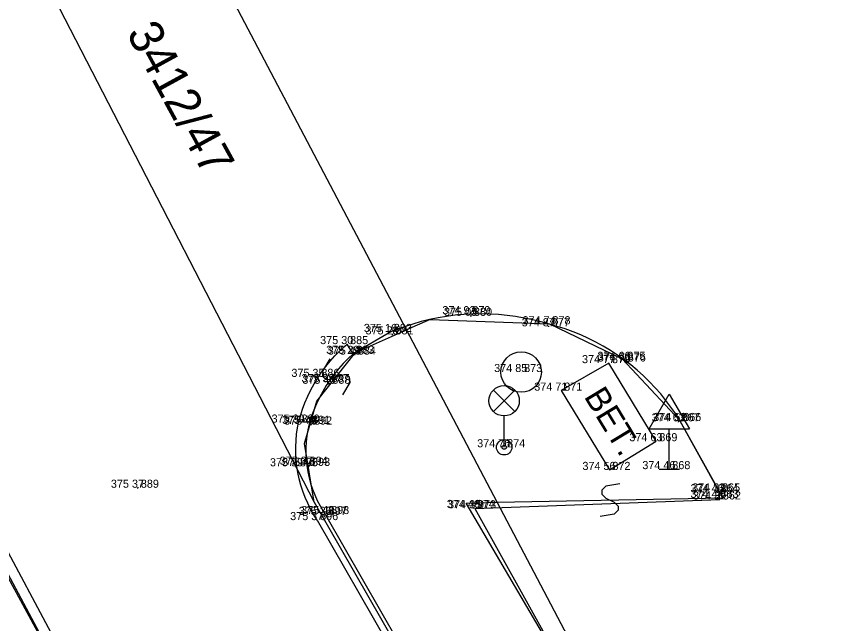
# Model space of a CAD drawing. Extents: x -601196 to -600262, y -1082523 to -1081922.
# Drawn here: x -600574.7 to -600554.22, y -1082123.8 to -1082108.8 of the extents above; entities that cross this region are included whole.
import ezdxf

# ---------------------------------------------------------------- set-up
doc = ezdxf.new("R2010")
doc.units = 0
for name, color, linetype in [('Vrstva 1', 7, 'Continuous'), ('Vrstva 10', 7, 'Continuous'), ('Vrstva 11', 7, 'Continuous'), ('Vrstva 2', 7, 'Continuous'), ('Vrstva 20', 7, 'Continuous'), ('Vrstva 27', 7, 'Continuous'), ('Vrstva 3', 7, 'Continuous'), ('Vrstva 33', 7, 'Continuous'), ('Vrstva 34', 7, 'Continuous'), ('Vrstva 40', 7, 'Continuous'), ('Vrstva 47', 7, 'Continuous')]:
    doc.layers.add(name, color=color, linetype=linetype)

msp = doc.modelspace()

# ---------------------------------------------------------------- linework, layer by layer
at = {"layer": 'Vrstva 1'}
for p, q in [((-600563.51, -1082116.16), (-600563.51, -1082116.16)), ((-600563.47, -1082116.2), (-600563.47, -1082116.2)), ((-600561.55, -1082116.46), (-600561.55, -1082116.46)), ((-600561.53, -1082116.41), (-600561.53, -1082116.41)), ((-600565.45, -1082116.6), (-600565.45, -1082116.6)), ((-600565.41, -1082116.66), (-600565.41, -1082116.66)), ((-600566.53, -1082116.9), (-600566.53, -1082116.9)), ((-600566.38, -1082117.14), (-600566.38, -1082117.14)), ((-600566.34, -1082117.16), (-600566.34, -1082117.16)), ((-600559.68, -1082117.29), (-600559.68, -1082117.29)), ((-600560.06, -1082117.37), (-600560.06, -1082117.37)), ((-600559.67, -1082117.33), (-600559.67, -1082117.33)), ((-600567.24, -1082117.71), (-600567.24, -1082117.71)), ((-600562.23, -1082117.59), (-600562.23, -1082117.59)), ((-600566.99, -1082117.84), (-600566.99, -1082117.84)), ((-600566.97, -1082117.88), (-600566.97, -1082117.88)), ((-600561.24, -1082118.05), (-600561.24, -1082118.05)), ((-600567.73, -1082118.84), (-600567.73, -1082118.84)), ((-600567.47, -1082118.87), (-600567.47, -1082118.87)), ((-600567.42, -1082118.89), (-600567.42, -1082118.89)), ((-600558.34, -1082118.81), (-600558.34, -1082118.81)), ((-600558.3, -1082118.8), (-600558.3, -1082118.8)), ((-600558.89, -1082119.3), (-600558.89, -1082119.3)), ((-600562.65, -1082119.45), (-600562.65, -1082119.45)), ((-600567.77, -1082119.92), (-600567.77, -1082119.92)), ((-600567.53, -1082119.88), (-600567.53, -1082119.88)), ((-600567.47, -1082119.91), (-600567.47, -1082119.91)), ((-600560.05, -1082120.01), (-600560.05, -1082120.01)), ((-600558.57, -1082119.99), (-600558.57, -1082119.99)), ((-600571.7, -1082120.45), (-600571.7, -1082120.45)), ((-600557.38, -1082120.56), (-600557.38, -1082120.56)), ((-600557.34, -1082120.54), (-600557.34, -1082120.54)), ((-600557.38, -1082120.7), (-600557.38, -1082120.7)), ((-600557.32, -1082120.74), (-600557.32, -1082120.74)), ((-600563.4, -1082120.95), (-600563.4, -1082120.95)), ((-600563.37, -1082120.96), (-600563.37, -1082120.96)), ((-600567.06, -1082121.12), (-600567.06, -1082121.12)), ((-600567, -1082121.1), (-600567, -1082121.1)), ((-600567.27, -1082121.25), (-600567.27, -1082121.25))]:
    msp.add_line(p, q, dxfattribs=at)
at = {"layer": 'Vrstva 10'}
for p, q in [((-600565.45, -1082116.6), (-600566.38, -1082117.14)), ((-600557.34, -1082120.54), (-600558.3, -1082118.8)), ((-600557.32, -1082120.74), (-600557.34, -1082120.54)), ((-600563.37, -1082120.96), (-600557.32, -1082120.74)), ((-600567.11, -1082137.17), (-600575.77, -1082120.97)), ((-600563.37, -1082120.96), (-600560.5, -1082126.14)), ((-600567.06, -1082121.12), (-600561.14, -1082131.44))]:
    msp.add_line(p, q, dxfattribs=at)
for points in [[(-600561.53, -1082116.41), (-600561.736, -1082116.351), (-600561.944, -1082116.299), (-600562.154, -1082116.255), (-600562.366, -1082116.219), (-600562.578, -1082116.19), (-600562.791, -1082116.17), (-600563.005, -1082116.158), (-600563.219, -1082116.153), (-600563.433, -1082116.157), (-600563.647, -1082116.168), (-600563.86, -1082116.188), (-600564.072, -1082116.215), (-600564.283, -1082116.25), (-600564.492, -1082116.293), (-600564.699, -1082116.344), (-600564.905, -1082116.403), (-600565.108, -1082116.469), (-600565.308, -1082116.542), (-600565.45, -1082116.6)], [(-600558.3, -1082118.8), (-600558.41, -1082118.626), (-600558.528, -1082118.457), (-600558.651, -1082118.292), (-600558.781, -1082118.132), (-600558.917, -1082117.978), (-600559.059, -1082117.828), (-600559.207, -1082117.684), (-600559.36, -1082117.546), (-600559.518, -1082117.414), (-600559.682, -1082117.289), (-600559.85, -1082117.169), (-600560.023, -1082117.056), (-600560.2, -1082116.95), (-600560.381, -1082116.851), (-600560.565, -1082116.759), (-600560.753, -1082116.674), (-600560.945, -1082116.597), (-600561.139, -1082116.526), (-600561.336, -1082116.464), (-600561.53, -1082116.41)], [(-600566.38, -1082117.14), (-600566.505, -1082117.257), (-600566.625, -1082117.38), (-600566.739, -1082117.508), (-600566.847, -1082117.641), (-600566.948, -1082117.779), (-600567.044, -1082117.922), (-600567.132, -1082118.069), (-600567.213, -1082118.22), (-600567.288, -1082118.375), (-600567.355, -1082118.533), (-600567.414, -1082118.694), (-600567.466, -1082118.858), (-600567.47, -1082118.87)], [(-600567.47, -1082118.87), (-600567.502, -1082119.016), (-600567.526, -1082119.163), (-600567.542, -1082119.312), (-600567.55, -1082119.461), (-600567.55, -1082119.611), (-600567.542, -1082119.76), (-600567.526, -1082119.908), (-600567.503, -1082120.056), (-600567.471, -1082120.202), (-600567.432, -1082120.346), (-600567.384, -1082120.488), (-600567.33, -1082120.627), (-600567.268, -1082120.763), (-600567.199, -1082120.896), (-600567.123, -1082121.025), (-600567.06, -1082121.12)]]:
    msp.add_lwpolyline(points, dxfattribs=at)
at = {"layer": 'Vrstva 11'}
for p, q in [((-600566.38, -1082117.14), (-600566.53, -1082116.9)), ((-600560.06, -1082117.37), (-600561.24, -1082118.05)), ((-600558.89, -1082119.3), (-600560.06, -1082117.37)), ((-600561.24, -1082118.05), (-600560.05, -1082120.01)), ((-600560.05, -1082120.01), (-600558.89, -1082119.3)), ((-600566.89, -1082137.01), (-600575.53, -1082120.88)), ((-600567.27, -1082121.25), (-600561.37, -1082131.55))]:
    msp.add_line(p, q, dxfattribs=at)
for points in [[(-600567.73, -1082118.84), (-600567.684, -1082118.673), (-600567.631, -1082118.509), (-600567.571, -1082118.347), (-600567.502, -1082118.188), (-600567.427, -1082118.033), (-600567.345, -1082117.881), (-600567.255, -1082117.734), (-600567.159, -1082117.59), (-600567.056, -1082117.451), (-600566.947, -1082117.317), (-600566.832, -1082117.189), (-600566.711, -1082117.065), (-600566.585, -1082116.948), (-600566.53, -1082116.9)], [(-600567.27, -1082121.25), (-600567.355, -1082121.115), (-600567.432, -1082120.976), (-600567.503, -1082120.833), (-600567.567, -1082120.687), (-600567.623, -1082120.538), (-600567.671, -1082120.386), (-600567.712, -1082120.232), (-600567.745, -1082120.076), (-600567.77, -1082119.919), (-600567.787, -1082119.761), (-600567.797, -1082119.602), (-600567.798, -1082119.442), (-600567.791, -1082119.283), (-600567.777, -1082119.124), (-600567.754, -1082118.967), (-600567.73, -1082118.84)]]:
    msp.add_lwpolyline(points, dxfattribs=at)
at = {"layer": 'Vrstva 20'}
for p, q in [((-600563.48, -1082116.2), (-600563.46, -1082116.2)), ((-600563.47, -1082116.185), (-600563.47, -1082116.2)), ((-600563.47, -1082116.215), (-600563.47, -1082116.2)), ((-600561.56, -1082116.46), (-600561.54, -1082116.46)), ((-600561.55, -1082116.445), (-600561.55, -1082116.46)), ((-600561.55, -1082116.475), (-600561.55, -1082116.46)), ((-600565.42, -1082116.66), (-600565.4, -1082116.66)), ((-600565.41, -1082116.645), (-600565.41, -1082116.66)), ((-600565.41, -1082116.675), (-600565.41, -1082116.66)), ((-600566.35, -1082117.16), (-600566.33, -1082117.16)), ((-600566.34, -1082117.145), (-600566.34, -1082117.16)), ((-600566.34, -1082117.175), (-600566.34, -1082117.16)), ((-600559.67, -1082117.315), (-600559.67, -1082117.33)), ((-600559.68, -1082117.33), (-600559.66, -1082117.33)), ((-600559.67, -1082117.345), (-600559.67, -1082117.33)), ((-600566.98, -1082117.88), (-600566.96, -1082117.88)), ((-600566.97, -1082117.865), (-600566.97, -1082117.88)), ((-600566.97, -1082117.895), (-600566.97, -1082117.88)), ((-600567.43, -1082118.89), (-600567.41, -1082118.89)), ((-600567.42, -1082118.875), (-600567.42, -1082118.89)), ((-600567.42, -1082118.905), (-600567.42, -1082118.89)), ((-600558.35, -1082118.81), (-600558.33, -1082118.81)), ((-600558.34, -1082118.795), (-600558.34, -1082118.81)), ((-600558.34, -1082118.825), (-600558.34, -1082118.81)), ((-600567.48, -1082119.91), (-600567.46, -1082119.91)), ((-600567.47, -1082119.895), (-600567.47, -1082119.91)), ((-600567.47, -1082119.925), (-600567.47, -1082119.91)), ((-600571.71, -1082120.45), (-600571.69, -1082120.45)), ((-600571.7, -1082120.435), (-600571.7, -1082120.45)), ((-600571.7, -1082120.465), (-600571.7, -1082120.45)), ((-600557.39, -1082120.56), (-600557.37, -1082120.56)), ((-600557.38, -1082120.545), (-600557.38, -1082120.56)), ((-600557.38, -1082120.575), (-600557.38, -1082120.56)), ((-600557.39, -1082120.7), (-600557.37, -1082120.7)), ((-600557.38, -1082120.685), (-600557.38, -1082120.7)), ((-600557.38, -1082120.715), (-600557.38, -1082120.7)), ((-600563.41, -1082120.95), (-600563.39, -1082120.95)), ((-600563.4, -1082120.935), (-600563.4, -1082120.95)), ((-600563.4, -1082120.965), (-600563.4, -1082120.95)), ((-600567.01, -1082121.1), (-600566.99, -1082121.1)), ((-600567, -1082121.085), (-600567, -1082121.1)), ((-600567, -1082121.115), (-600567, -1082121.1))]:
    msp.add_line(p, q, dxfattribs=at)
at = {"layer": 'Vrstva 27'}
msp.add_circle((-600562.23, -1082117.59), 0.5, dxfattribs=at)
at = {"layer": 'Vrstva 33'}
for p, q in [((-600562.915, -1082118.035), (-600562.385, -1082118.565)), ((-600562.915, -1082118.565), (-600562.385, -1082118.035)), ((-600562.65, -1082119.45), (-600562.65, -1082118.675))]:
    msp.add_line(p, q, dxfattribs=at)
for centre, radius in [((-600562.65, -1082118.3), 0.375), ((-600562.65, -1082119.45), 0.19), ((-600562.65, -1082119.45), 0.05)]:
    msp.add_circle(centre, radius, dxfattribs=at)
at = {"layer": 'Vrstva 34'}
for p, q in [((-600559.07, -1082118.99), (-600558.57, -1082118.14)), ((-600558.57, -1082118.14), (-600558.07, -1082118.99)), ((-600559.07, -1082118.99), (-600558.07, -1082118.99)), ((-600558.57, -1082119.99), (-600558.57, -1082118.99)), ((-600558.82, -1082119.99), (-600558.32, -1082119.99))]:
    msp.add_line(p, q, dxfattribs=at)
at = {"layer": 'Vrstva 47'}
for p, q in [((-600565.06, -1082116.55), (-600571.27, -1082104.74)), ((-600574.37, -1082107.17), (-600567.34, -1082120.81)), ((-600580.35, -1082112.71), (-600573.4, -1082125.43)), ((-600564.48, -1082116.29), (-600565.06, -1082116.55)), ((-600564.48, -1082116.29), (-600561.53, -1082116.4)), ((-600561.53, -1082116.4), (-600559.73, -1082117.26)), ((-600566.32, -1082117.11), (-600565.06, -1082116.55)), ((-600562.82, -1082120.81), (-600565.06, -1082116.55)), ((-600567.28, -1082118.31), (-600566.32, -1082117.11)), ((-600566.956, -1082117.264), (-600567.135, -1082117.569)), ((-600559.73, -1082117.26), (-600558.32, -1082118.78)), ((-600567.135, -1082117.569), (-600567.12, -1082117.71)), ((-600567.12, -1082117.71), (-600567.042, -1082117.772)), ((-600566.901, -1082117.756), (-600566.698, -1082117.663)), ((-600566.698, -1082117.663), (-600566.557, -1082117.647)), ((-600566.557, -1082117.647), (-600566.479, -1082117.71)), ((-600566.479, -1082117.71), (-600566.464, -1082117.85)), ((-600567.042, -1082117.772), (-600566.901, -1082117.756)), ((-600566.464, -1082117.85), (-600566.643, -1082118.155)), ((-600567.58, -1082119.36), (-600567.28, -1082118.31)), ((-600558.32, -1082118.78), (-600557.25, -1082120.7)), ((-600567.34, -1082120.81), (-600567.58, -1082119.36)), ((-600559.792, -1082120.35), (-600560.141, -1082120.407)), ((-600560.141, -1082120.407), (-600560.239, -1082120.509)), ((-600560.239, -1082120.509), (-600560.237, -1082120.608)), ((-600562.82, -1082120.81), (-600557.25, -1082120.7)), ((-600560.237, -1082120.608), (-600560.135, -1082120.706)), ((-600560.135, -1082120.706), (-600559.934, -1082120.803)), ((-600567.34, -1082120.81), (-600559.86, -1082133.86)), ((-600563.59, -1082120.83), (-600562.82, -1082120.81)), ((-600560.45, -1082126.17), (-600563.59, -1082120.83)), ((-600551.63, -1082142.08), (-600562.82, -1082120.81)), ((-600559.934, -1082120.803), (-600559.832, -1082120.901)), ((-600559.83, -1082121.001), (-600559.928, -1082121.102)), ((-600559.832, -1082120.901), (-600559.83, -1082121.001)), ((-600559.928, -1082121.102), (-600560.277, -1082121.159))]:
    msp.add_line(p, q, dxfattribs=at)

# ---------------------------------------------------------------- texts
at = {"layer": 'Vrstva 2'}
for s, p in [(' 879', (-600563.51, -1082116.16)), (' 880', (-600563.47, -1082116.2)), (' 877', (-600561.55, -1082116.46)), (' 878', (-600561.53, -1082116.41)), (' 882', (-600565.45, -1082116.6)), (' 881', (-600565.41, -1082116.66)), (' 885', (-600566.53, -1082116.9)), (' 883', (-600566.38, -1082117.14)), (' 884', (-600566.34, -1082117.16)), (' 875', (-600559.68, -1082117.29)), (' 870', (-600560.06, -1082117.37)), (' 876', (-600559.67, -1082117.33)), (' 886', (-600567.24, -1082117.71)), (' 873', (-600562.23, -1082117.59)), (' 887', (-600566.99, -1082117.84)), (' 888', (-600566.97, -1082117.88)), (' 871', (-600561.24, -1082118.05)), (' 890', (-600567.73, -1082118.84)), (' 891', (-600567.47, -1082118.87)), (' 892', (-600567.42, -1082118.89)), (' 867', (-600558.34, -1082118.81)), (' 866', (-600558.3, -1082118.8)), (' 869', (-600558.89, -1082119.3)), (' 874', (-600562.65, -1082119.45)), (' 895', (-600567.77, -1082119.92)), (' 894', (-600567.53, -1082119.88)), (' 893', (-600567.47, -1082119.91)), (' 872', (-600560.05, -1082120.01)), (' 868', (-600558.57, -1082119.99)), (' 889', (-600571.7, -1082120.45)), (' 864', (-600557.38, -1082120.56)), (' 865', (-600557.34, -1082120.54)), (' 863', (-600557.38, -1082120.7)), (' 862', (-600557.32, -1082120.74)), (' 974', (-600563.4, -1082120.95)), (' 973', (-600563.37, -1082120.96)), (' 897', (-600567.06, -1082121.12)), (' 898', (-600567, -1082121.1)), (' 896', (-600567.27, -1082121.25))]:
    msp.add_text(s, height=0.2, dxfattribs=at).set_placement(p)
at = {"layer": 'Vrstva 3'}
for s, p in [('374 92 ', (-600564.176, -1082116.16)), ('375 05 ', (-600564.136, -1082116.2)), ('374 87 ', (-600562.216, -1082116.46)), ('374 74 ', (-600562.196, -1082116.41)), ('375 16 ', (-600566.116, -1082116.6)), ('375 28 ', (-600566.076, -1082116.66)), ('375 30 ', (-600567.196, -1082116.9)), ('375 29 ', (-600567.046, -1082117.14)), ('375 40 ', (-600567.006, -1082117.16)), ('374 66 ', (-600560.346, -1082117.29)), ('374 77 ', (-600560.726, -1082117.37)), ('374 76 ', (-600560.336, -1082117.33)), ('375 35 ', (-600567.906, -1082117.71)), ('374 85 ', (-600562.896, -1082117.59)), ('375 35 ', (-600567.656, -1082117.84)), ('375 46 ', (-600567.636, -1082117.88)), ('374 71 ', (-600561.906, -1082118.05)), ('375 39 ', (-600568.396, -1082118.84)), ('375 40 ', (-600568.136, -1082118.87)), ('375 48 ', (-600568.086, -1082118.89)), ('374 63 ', (-600559.006, -1082118.81)), ('374 52 ', (-600558.966, -1082118.8)), ('374 63 ', (-600559.556, -1082119.3)), ('374 76 ', (-600563.316, -1082119.45)), ('375 39 ', (-600568.436, -1082119.92)), ('375 37 ', (-600568.196, -1082119.88)), ('375 48 ', (-600568.136, -1082119.91)), ('374 56 ', (-600560.716, -1082120.01)), ('374 46 ', (-600559.236, -1082119.99)), ('375 37 ', (-600572.366, -1082120.45)), ('374 46 ', (-600558.046, -1082120.56)), ('374 33 ', (-600558.006, -1082120.54)), ('374 44 ', (-600558.046, -1082120.7)), ('374 32 ', (-600557.986, -1082120.74)), ('374 46 ', (-600564.066, -1082120.95)), ('374 35 ', (-600564.036, -1082120.96)), ('375 35 ', (-600567.726, -1082121.12)), ('375 48 ', (-600567.666, -1082121.1)), ('375 37 ', (-600567.936, -1082121.25))]:
    msp.add_text(s, height=0.2, dxfattribs=at).set_placement(p)
at = {"layer": 'Vrstva 40'}
msp.add_text('BET.', height=0.6, rotation=301.2637, dxfattribs=at).set_placement((-600560.69, -1082118.194))
at = {"layer": 'Vrstva 47'}
msp.add_text('3412/47', height=0.85, rotation=298.6996, dxfattribs=at).set_placement((-600571.995, -1082109.217))

doc.saveas('drawing.dxf')
